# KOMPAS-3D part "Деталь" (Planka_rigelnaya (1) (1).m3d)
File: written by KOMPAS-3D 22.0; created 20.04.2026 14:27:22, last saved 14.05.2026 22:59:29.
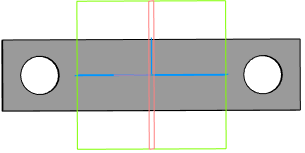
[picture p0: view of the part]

Document properties: Автор: TMK; Полное имя файла: E:\test_kompas\all_v20\Planka_rigelnaya (1) (1).m3d; Организация: TMK

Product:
- Part/product: Деталь
    Масса: 0.134151

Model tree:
1. Эскиз:1
2. Элемент выдавливания:1
     Расстояние 2 = 8
3. Эскиз:2
4. Элемент выдавливания:2
     Расстояние 2 = 10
